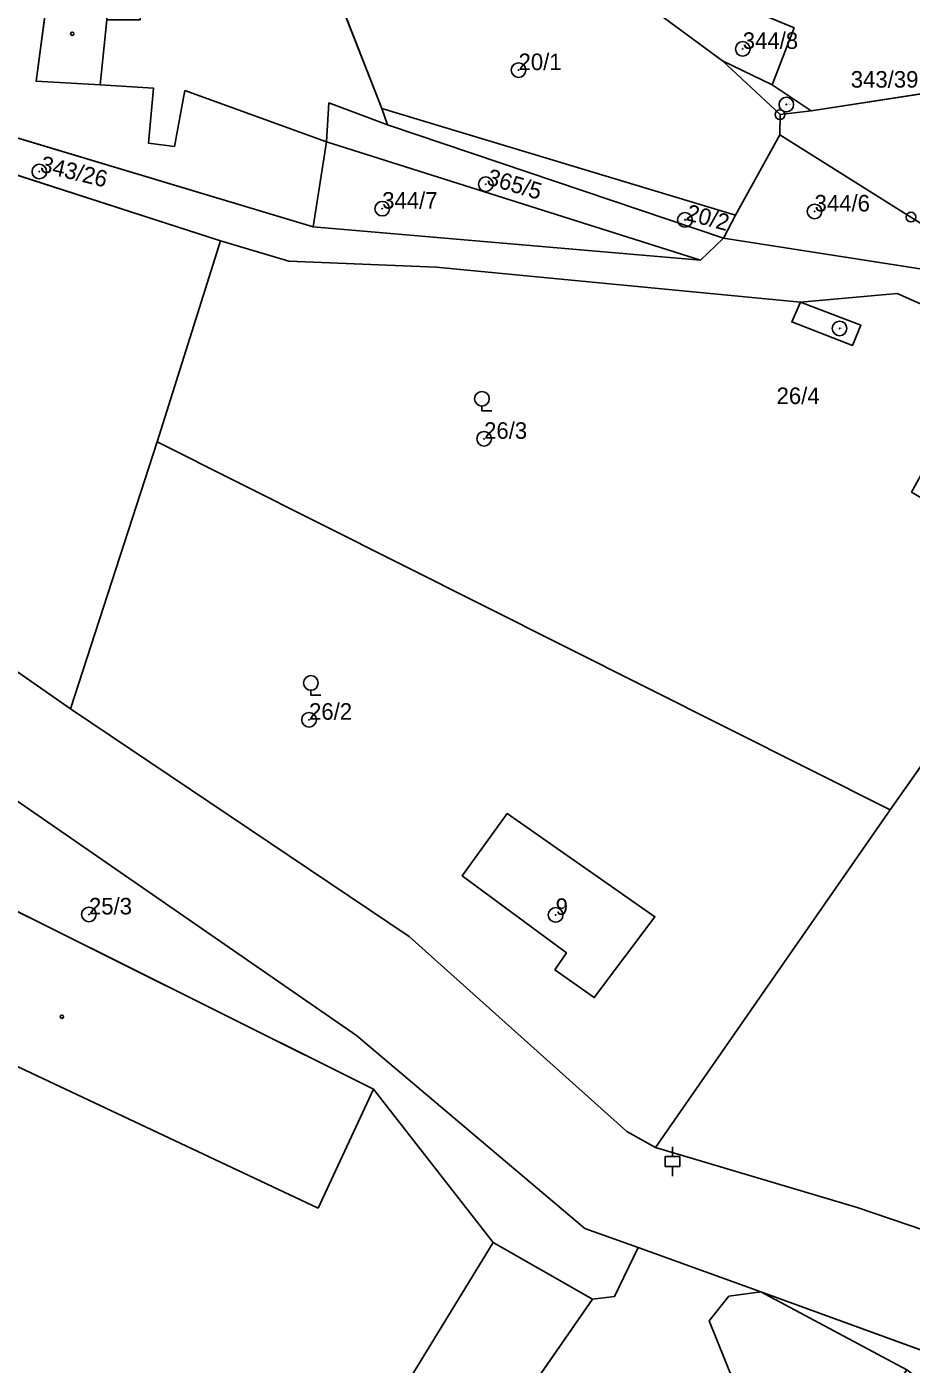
# Model space of a CAD drawing. Extents: x -652854 to -650068, y -1097661 to -1095417.
# Drawn here: x -651004.4 to -650913.5, y -1095999.2 to -1095861.8 of the extents above; entities that cross this region are included whole.
import ezdxf

# ---------------------------------------------------------------- set-up
doc = ezdxf.new("R2010")
doc.units = 0
for name, color, linetype in [('Definiční body parcel', 7, 'Continuous'), ('Geodetické body', 7, 'Continuous'), ('Hranice - vnitř_ kresba', 7, 'Continuous'), ('Hranice parcel', 7, 'Continuous'), ('Obvody jako plochy', 7, 'Continuous'), ('Ostatní mapové značky 1', 7, 'Continuous'), ('Parcelní čísla', 7, 'Continuous'), ('Prvky pro prodl_ par_ č_', 7, 'Continuous'), ('Značky kultur', 7, 'Continuous'), ('Značky na budově ne v SPI', 7, 'Continuous')]:
    doc.layers.add(name, color=color, linetype=linetype)

msp = doc.modelspace()

# ---------------------------------------------------------------- linework, layer by layer
at = {"layer": 'Definiční body parcel'}
for centre, radius in [((-650930.82, -1095864.05), 0.75), ((-650930.82, -1095864.05), 0.0327), ((-650953.86, -1095866.23), 0.75), ((-650953.86, -1095866.23), 0.0327), ((-650926.34, -1095869.77), 0.75), ((-650926.34, -1095869.77), 0.0327), ((-651003.11, -1095876.66), 0.75), ((-651003.11, -1095876.66), 0.0327), ((-650957.23, -1095877.96), 0.75), ((-650957.23, -1095877.96), 0.0327), ((-650967.87, -1095880.47), 0.75), ((-650967.87, -1095880.47), 0.0327), ((-650923.44, -1095880.76), 0.75), ((-650936.76, -1095881.62), 0.75), ((-650936.76, -1095881.62), 0.0327), ((-650923.44, -1095880.76), 0.0327), ((-650920.87, -1095892.78), 0.75), ((-650920.87, -1095892.78), 0.0327), ((-650957.4, -1095904.12), 0.75), ((-650957.4, -1095904.12), 0.0327), ((-650975.39, -1095932.99), 0.75), ((-650975.39, -1095932.99), 0.0327), ((-650998.01, -1095953), 0.75), ((-650998.01, -1095953), 0.0327), ((-650950.05, -1095953.05), 0.75), ((-650950.05, -1095953.05), 0.0327)]:
    msp.add_circle(centre, radius, dxfattribs=at)
at = {"layer": 'Geodetické body'}
for centre, radius in [((-650926.99, -1095870.8), 0.5), ((-650926.99, -1095870.8), 0.001), ((-650913.54, -1095881.34), 0.5), ((-650913.54, -1095881.34), 0.001)]:
    msp.add_circle(centre, radius, dxfattribs=at)
at = {"layer": 'Hranice - vnitř_ kresba'}
for p, q in [((-650996.17, -1095861.07), (-650996.85, -1095867.76)), ((-650974.45, -1095983.2), (-651022.36, -1095960.61)), ((-650968.76, -1095970.97), (-650974.45, -1095983.2)), ((-650956.46, -1095986.73), (-650977.88, -1096021.61))]:
    msp.add_line(p, q, dxfattribs=at)
at = {"layer": 'Hranice parcel'}
for p, q in [((-650967.9, -1095870.16), (-650976.75, -1095847.66)), ((-650932.9, -1095865.27), (-650946.14, -1095855.5)), ((-651001.98, -1095856.46), (-651003.42, -1095867.37)), ((-650934.64, -1095858.09), (-650925.55, -1095861.88)), ((-650925.55, -1095861.88), (-650927.79, -1095867.74)), ((-650932.9, -1095865.27), (-650926.99, -1095870.8)), ((-650927.79, -1095867.74), (-650932.9, -1095865.27)), ((-650974.96, -1095882.35), (-651022.27, -1095868.13)), ((-651003.42, -1095867.37), (-650996.85, -1095867.76)), ((-650996.85, -1095867.76), (-650991.37, -1095868.09)), ((-650991.37, -1095868.09), (-650991.88, -1095873.74)), ((-650923.79, -1095870.4), (-650927.79, -1095867.74)), ((-650923.79, -1095870.4), (-650907.46, -1095867.89)), ((-650989.22, -1095874.08), (-650988.14, -1095868.33)), ((-650988.14, -1095868.33), (-650973.58, -1095873.61)), ((-650973.36, -1095869.6), (-650973.58, -1095873.61)), ((-650967.34, -1095871.86), (-650973.36, -1095869.6)), ((-650931.56, -1095881.13), (-650967.9, -1095870.16)), ((-650967.34, -1095871.86), (-650967.9, -1095870.16)), ((-650926.99, -1095870.8), (-650927, -1095872.87)), ((-650926.99, -1095870.8), (-650923.79, -1095870.4)), ((-651022.11, -1095871.64), (-650984.48, -1095883.78)), ((-650932.81, -1095883.5), (-650967.34, -1095871.86)), ((-650973.58, -1095873.61), (-650974.96, -1095882.35)), ((-650973.58, -1095873.61), (-650935.17, -1095885.77)), ((-650931.56, -1095881.13), (-650927, -1095872.87)), ((-650913.54, -1095881.34), (-650927, -1095872.87)), ((-650991.88, -1095873.74), (-650989.22, -1095874.08)), ((-650932.81, -1095883.5), (-650931.56, -1095881.13)), ((-650902.68, -1095888.18), (-650913.54, -1095881.34)), ((-650999.89, -1095931.88), (-651069.69, -1095883.2)), ((-650935.17, -1095885.77), (-650974.96, -1095882.35)), ((-650984.48, -1095883.78), (-650991.01, -1095904.42)), ((-650984.48, -1095883.78), (-650977.45, -1095885.85)), ((-650935.17, -1095885.77), (-650932.81, -1095883.5)), ((-650932.81, -1095883.5), (-650902.68, -1095888.18)), ((-650977.45, -1095885.85), (-650962.32, -1095886.47)), ((-650962.32, -1095886.47), (-650924.87, -1095890.09)), ((-650925.78, -1095892.11), (-650924.87, -1095890.09)), ((-650924.87, -1095890.09), (-650914.96, -1095889.2)), ((-650924.87, -1095890.09), (-650918.68, -1095892.45)), ((-650914.96, -1095889.2), (-650909.84, -1095891.45)), ((-650919.55, -1095894.52), (-650925.78, -1095892.11)), ((-650918.68, -1095892.45), (-650919.55, -1095894.52)), ((-650991.01, -1095904.42), (-650999.89, -1095931.88)), ((-650991.01, -1095904.42), (-650915.66, -1095942.26)), ((-650999.89, -1095931.88), (-650965.11, -1095955.28)), ((-650915.66, -1095942.26), (-650908.63, -1095932.22)), ((-651006, -1095940.92), (-650970.52, -1095965.45)), ((-650915.66, -1095942.26), (-650939.79, -1095976.94)), ((-650955.03, -1095942.64), (-650959.67, -1095949.02)), ((-650939.84, -1095953.23), (-650955.03, -1095942.64)), ((-650959.67, -1095949.02), (-650948.94, -1095956.96)), ((-651011.17, -1095949.81), (-650968.76, -1095970.97)), ((-650946.08, -1095961.54), (-650939.84, -1095953.23)), ((-650965.11, -1095955.28), (-650942.73, -1095975.31)), ((-650948.94, -1095956.96), (-650950.13, -1095958.68)), ((-650950.13, -1095958.68), (-650946.08, -1095961.54)), ((-650970.52, -1095965.45), (-650947.06, -1095985.27)), ((-650968.76, -1095970.97), (-650956.46, -1095986.73)), ((-650939.79, -1095976.94), (-650942.73, -1095975.31)), ((-650919.07, -1095983.1), (-650939.79, -1095976.94)), ((-650906.97, -1095987.24), (-650919.07, -1095983.1)), ((-650947.06, -1095985.27), (-650941.58, -1095987.24)), ((-650956.46, -1095986.73), (-650946.25, -1095992.54)), ((-650943.99, -1095992.27), (-650941.58, -1095987.24)), ((-650941.58, -1095987.24), (-650928.95, -1095991.79)), ((-650928.95, -1095991.79), (-650932.24, -1095992.24)), ((-650913.95, -1095999.79), (-650928.95, -1095991.79)), ((-650928.95, -1095991.79), (-650910.04, -1095998.66)), ((-650959.24, -1096011.23), (-650946.25, -1095992.54)), ((-650946.25, -1095992.54), (-650943.99, -1095992.27)), ((-650932.24, -1095992.24), (-650934.27, -1095994.75)), ((-650934.27, -1095994.75), (-650930.14, -1096005.05))]:
    msp.add_line(p, q, dxfattribs=at)
at = {"layer": 'Obvody jako plochy'}
for points in [[(-650950.21, -1095830.99), (-650955.12, -1095851.96), (-650946.14, -1095855.5), (-650934.64, -1095858.09), (-650925.55, -1095861.88), (-650927.79, -1095867.74), (-650923.79, -1095870.4), (-650907.46, -1095867.89), (-650903.19, -1095859.94), (-650863.63, -1095883.27), (-650857.68, -1095897.96), (-650843.17, -1095879.48), (-650888.99, -1095851.28), (-650885.3, -1095832.78), (-650897.08, -1095826.41), (-650916.2, -1095812.16), (-650931.45, -1095804.19)], [(-650976.15, -1095842.33), (-650976.75, -1095847.66), (-650967.9, -1095870.16), (-650931.56, -1095881.13), (-650927, -1095872.87), (-650926.99, -1095870.8), (-650932.9, -1095865.27), (-650946.14, -1095855.5), (-650955.12, -1095851.96), (-650961.09, -1095848.7), (-650973.43, -1095841.37), (-650975.9, -1095839.98)], [(-650986.05, -1095846.82), (-650986.12, -1095847.71), (-650991.74, -1095847.48), (-650991.99, -1095852.3), (-650990.01, -1095852.5), (-650990.12, -1095854.4), (-650992.11, -1095854.32), (-650992.74, -1095861.06), (-650996.17, -1095861.07), (-650995.87, -1095857.06), (-651001.98, -1095856.46), (-651003.42, -1095867.37), (-650996.85, -1095867.76), (-650991.37, -1095868.09), (-650991.88, -1095873.74), (-650989.22, -1095874.08), (-650988.14, -1095868.33), (-650973.58, -1095873.61), (-650973.36, -1095869.6), (-650967.34, -1095871.86), (-650967.9, -1095870.16), (-650976.75, -1095847.66)], [(-650927.79, -1095867.74), (-650925.55, -1095861.88), (-650934.64, -1095858.09), (-650946.14, -1095855.5), (-650932.9, -1095865.27)], [(-650926.99, -1095870.8), (-650927, -1095872.87), (-650913.54, -1095881.34), (-650902.68, -1095888.18), (-650891.03, -1095894.51), (-650877.77, -1095901.83), (-650863.63, -1095883.27), (-650903.19, -1095859.94), (-650907.46, -1095867.89), (-650923.79, -1095870.4)], [(-650927.79, -1095867.74), (-650932.9, -1095865.27), (-650926.99, -1095870.8), (-650923.79, -1095870.4)], [(-650973.58, -1095873.61), (-650935.17, -1095885.77), (-650932.81, -1095883.5), (-650967.34, -1095871.86), (-650973.36, -1095869.6)], [(-651034.02, -1095870.19), (-651054.86, -1095870.49), (-651088.16, -1095874.33), (-651069.69, -1095883.2), (-650999.89, -1095931.88), (-650991.01, -1095904.42), (-650984.48, -1095883.78), (-651022.11, -1095871.64)], [(-650967.34, -1095871.86), (-650932.81, -1095883.5), (-650931.56, -1095881.13), (-650967.9, -1095870.16)], [(-650973.58, -1095873.61), (-650974.96, -1095882.35), (-650935.17, -1095885.77)], [(-650931.56, -1095881.13), (-650932.81, -1095883.5), (-650902.68, -1095888.18), (-650913.54, -1095881.34), (-650927, -1095872.87)], [(-650914.96, -1095889.2), (-650924.87, -1095890.09), (-650962.32, -1095886.47), (-650977.45, -1095885.85), (-650984.48, -1095883.78), (-650991.01, -1095904.42), (-650915.66, -1095942.26), (-650908.63, -1095932.22), (-650907.39, -1095930.49), (-650902.94, -1095924.22), (-650898.83, -1095918.21), (-650913.47, -1095909.59), (-650904.34, -1095892.99), (-650907.17, -1095891.31), (-650909.84, -1095891.45)], [(-650924.87, -1095890.09), (-650918.68, -1095892.45), (-650919.55, -1095894.52), (-650925.78, -1095892.11)], [(-650924.87, -1095890.09), (-650925.78, -1095892.11), (-650919.55, -1095894.52), (-650918.68, -1095892.45)], [(-650939.79, -1095976.94), (-650915.66, -1095942.26), (-650991.01, -1095904.42), (-650999.89, -1095931.88), (-650965.11, -1095955.28), (-650942.73, -1095975.31)], [(-650919.07, -1095983.1), (-650906.97, -1095987.24), (-650877.8, -1095945.22), (-650880.92, -1095939.45), (-650885.57, -1095945.44), (-650887.79, -1095943.89), (-650889.01, -1095945.42), (-650908.63, -1095932.22), (-650915.66, -1095942.26), (-650939.79, -1095976.94)], [(-651006, -1095940.92), (-651011.17, -1095949.81), (-650968.76, -1095970.97), (-650956.46, -1095986.73), (-650946.25, -1095992.54), (-650943.99, -1095992.27), (-650941.58, -1095987.24), (-650947.06, -1095985.27), (-650970.52, -1095965.45)], [(-650950.13, -1095958.68), (-650946.08, -1095961.54), (-650939.84, -1095953.23), (-650955.03, -1095942.64), (-650959.67, -1095949.02), (-650948.94, -1095956.96)], [(-650950.13, -1095958.68), (-650948.94, -1095956.96), (-650959.67, -1095949.02), (-650955.03, -1095942.64), (-650939.84, -1095953.23), (-650946.08, -1095961.54)], [(-650928.95, -1095991.79), (-650941.58, -1095987.24), (-650943.99, -1095992.27), (-650946.25, -1095992.54), (-650959.24, -1096011.23), (-650948.93, -1096017.64), (-650954.29, -1096026.46), (-650958.9, -1096023.69), (-650976.4, -1096052.35), (-650923.91, -1096091.54), (-650915.34, -1096072.03), (-650914.12, -1096069.22), (-650936.73, -1096059.52), (-650935.88, -1096057.57), (-650947.07, -1096048.17), (-650926.24, -1096020.58), (-650927.6, -1096019.54), (-650929.8, -1096017.97), (-650930.14, -1096005.05), (-650934.27, -1095994.75), (-650932.24, -1095992.24)], [(-650928.95, -1095991.79), (-650932.24, -1095992.24), (-650934.27, -1095994.75), (-650930.14, -1096005.05), (-650929.8, -1096017.97), (-650927.6, -1096019.54), (-650913.95, -1095999.79)], [(-650913.95, -1095999.79), (-650900.46, -1096009.94), (-650891.33, -1096018.28), (-650878.59, -1096032.13), (-650875.52, -1096037.79), (-650874.29, -1096030.48), (-650885.14, -1096017.44), (-650895.24, -1096007.92), (-650910.04, -1095998.66), (-650928.95, -1095991.79)]]:
    msp.add_lwpolyline(points, close=True, dxfattribs=at)
for points in [[(-651054.94, -1095856.32), (-651054.66, -1095867.16), (-651038.51, -1095866.83), (-651022.27, -1095868.13), (-650974.96, -1095882.35), (-650973.58, -1095873.61), (-650988.14, -1095868.33), (-650989.22, -1095874.08), (-650991.88, -1095873.74), (-650991.37, -1095868.09), (-650996.85, -1095867.76), (-651003.42, -1095867.37), (-651001.98, -1095856.46)], [(-650902.68, -1095888.18), (-650932.81, -1095883.5), (-650935.17, -1095885.77), (-650974.96, -1095882.35), (-651022.27, -1095868.13)], [(-650815.91, -1096079.94), (-650837.43, -1096057.82), (-650851.49, -1096042.56), (-650856.61, -1096037.55), (-650866.08, -1096025.56), (-650869.83, -1096021.1), (-650878.58, -1096010.13), (-650884.15, -1096004.16), (-650888.72, -1095999.9), (-650906.97, -1095987.24), (-650919.07, -1095983.1), (-650939.79, -1095976.94), (-650942.73, -1095975.31), (-650965.11, -1095955.28), (-650999.89, -1095931.88), (-651069.69, -1095883.2), (-651088.16, -1095874.33), (-651093.24, -1095871.75), (-651106.05, -1095871.75), (-651124.53, -1095872.94)], [(-651022.11, -1095871.64), (-650984.48, -1095883.78), (-650977.45, -1095885.85), (-650962.32, -1095886.47), (-650924.87, -1095890.09), (-650914.96, -1095889.2), (-650909.84, -1095891.45)], [(-651111.53, -1095882.37), (-651098.01, -1095884.51), (-651076.72, -1095891.08), (-651069.09, -1095896.55), (-651006, -1095940.92), (-650970.52, -1095965.45), (-650947.06, -1095985.27), (-650941.58, -1095987.24), (-650928.95, -1095991.79), (-650910.04, -1095998.66), (-650895.24, -1096007.92), (-650885.14, -1096017.44), (-650874.29, -1096030.48), (-650868.81, -1096038.2), (-650844.12, -1096064.27), (-650836.01, -1096073.17), (-650788.5, -1096124.42)], [(-651031.54, -1096014.05), (-650997.45, -1096032.13), (-650981.53, -1096040.37), (-650976.56, -1096031.8), (-650974.42, -1096033.09), (-650965.14, -1096019.73), (-650958.9, -1096023.69), (-650954.29, -1096026.46), (-650948.93, -1096017.64), (-650959.24, -1096011.23), (-650946.25, -1095992.54), (-650956.46, -1095986.73), (-650968.76, -1095970.97), (-651011.17, -1095949.81)]]:
    msp.add_lwpolyline(points, dxfattribs=at)
at = {"layer": 'Ostatní mapové značky 1'}
for p, q in [((-650938.05, -1095977.89), (-650938.05, -1095976.89)), ((-650938.05, -1095978.89), (-650938.05, -1095979.89))]:
    msp.add_line(p, q, dxfattribs=at)
msp.add_lwpolyline([(-650938.8, -1095978.89), (-650937.3, -1095978.89), (-650937.3, -1095977.89), (-650938.8, -1095977.89)], close=True, dxfattribs=at)
at = {"layer": 'Značky kultur'}
for p, q in [((-650957.62, -1095900.76), (-650957.62, -1095901.26)), ((-650957.62, -1095901.26), (-650956.597, -1095901.26)), ((-650975.2, -1095929.96), (-650975.2, -1095930.46)), ((-650975.2, -1095930.46), (-650974.177, -1095930.46))]:
    msp.add_line(p, q, dxfattribs=at)
for centre in [(-650957.62, -1095900.01), (-650975.2, -1095929.21)]:
    msp.add_circle(centre, 0.75, dxfattribs=at)
at = {"layer": 'Značky na budově ne v SPI'}
for centre in [(-650999.72, -1095862.49), (-651000.79, -1095963.51)]:
    msp.add_circle(centre, 0.175, dxfattribs=at)

# ---------------------------------------------------------------- texts
at = {"layer": 'Parcelní čísla'}
for s, height, p in [('344/8', 1.7, (-650930.82, -1095864.05)), ('20/1', 1.7, (-650953.86, -1095866.23)), ('343/39', 0.1, (-650926.34, -1095869.77)), ('344/7', 1.7, (-650967.87, -1095880.47)), ('344/6', 1.7, (-650923.44, -1095880.76)), ('26/4', 0.1, (-650920.87, -1095892.78)), ('26/3', 1.7, (-650957.4, -1095904.12)), ('26/2', 1.7, (-650975.39, -1095932.99)), ('25/3', 1.7, (-650998.01, -1095953)), ('9', 1.7, (-650950.05, -1095953.05))]:
    msp.add_text(s, height=height, dxfattribs=at).set_placement(p)
for s, rotation, p in [('343/26', 346.338, (-651003.11, -1095876.66)), ('365/5', 343.629, (-650957.23, -1095877.96)), ('20/2', 344.79, (-650936.76, -1095881.62))]:
    msp.add_text(s, height=1.7, rotation=rotation, dxfattribs=at).set_placement(p)
at = {"layer": 'Prvky pro prodl_ par_ č_'}
for s, p in [('343/39', (-650919.72, -1095868.03)), ('26/4', (-650927.344, -1095900.55))]:
    msp.add_text(s, height=1.7, dxfattribs=at).set_placement(p)

doc.saveas('drawing.dxf')
